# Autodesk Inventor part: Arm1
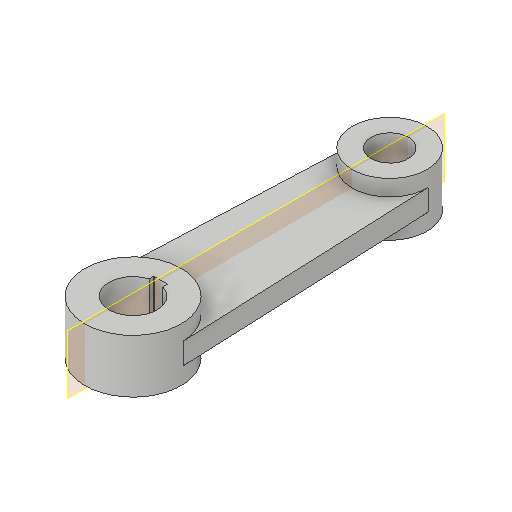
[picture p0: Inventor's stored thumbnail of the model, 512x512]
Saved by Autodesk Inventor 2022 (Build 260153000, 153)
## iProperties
Created: 2016-05
Part Number: Arm1
Material: Generic
Document SubType Name: Modeling
Designer: CADCIM
Density: 1 g/cm^3
Appearance: Default
Author: CADCIM
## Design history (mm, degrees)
sketch "Sketch1"
  geometry: C1 r 56.25 at (0, 0); C2 r 28 at (0, 0); C3 r 43.75 at (0, -300); C4 r 21.75 at (0, -300); 1 further point
  constraints: 4 centre point, 3 coincident
  dimensions: "d0" = 112.5 diameter of C1; "d1" = 56 diameter of C2; "d2" = 87.5 diameter of C3; "d3" = 43.5 diameter of C4; "d4" = 300 distance of C4.centre C2.centre
extrude "Extrusion1" new body sketch "Sketch1" stored distance "d5" = 62.5; taper "d6" = 0 deg
sketch "Sketch2"
  geometry: L1 (56.201, -2.344)-(43.712, -301.823); L2 (-56.201, -2.344)-(-43.712, -301.823); A1 r 56.25 centre (0, 0) between (-56.201, -2.344) and (56.201, -2.344); A2 r 43.75 centre (0, -300) between (43.712, -301.823) and (-43.712, -301.823); 3 further points
  constraints: 4 end point, 4 point on circle, 2 centre point, 2 coincident
extrude "Extrusion2" join sketch "Sketch2" stored distance "d7" = 25; taper "d8" = 0 deg
sketch "Sketch3"
  geometry: L1 (0, 0)-(0, 99.622); L2 (-8, 26.833)-(8, 26.833); L3 (8, 26.833)-(8, 32.3); L4 (8, 32.3)-(-8, 32.3); L5 (-8, 32.3)-(-8, 26.833); L6 (0, 0)-(0, -28); A1 r 28 centre (0, 0) between (-8, 26.833) and (8, 26.833) reference
  constraints: 12 end point, 3 point on circle, 2 parallel, 2 vertical, 1 horizontal, 1 perpendicular, 1 other
  dimensions: "d10" = 16 distance of L3.end L4.end; "d11" = 60.3 distance from line of L4 L6.end
extrude "Extrusion3" cut sketch "Sketch3" extent not by distance; stored distance "d12" = 25; taper "d13" = 0 deg
fillet "Fillet1" dims "d14" = 0.4
body "Solid1"
